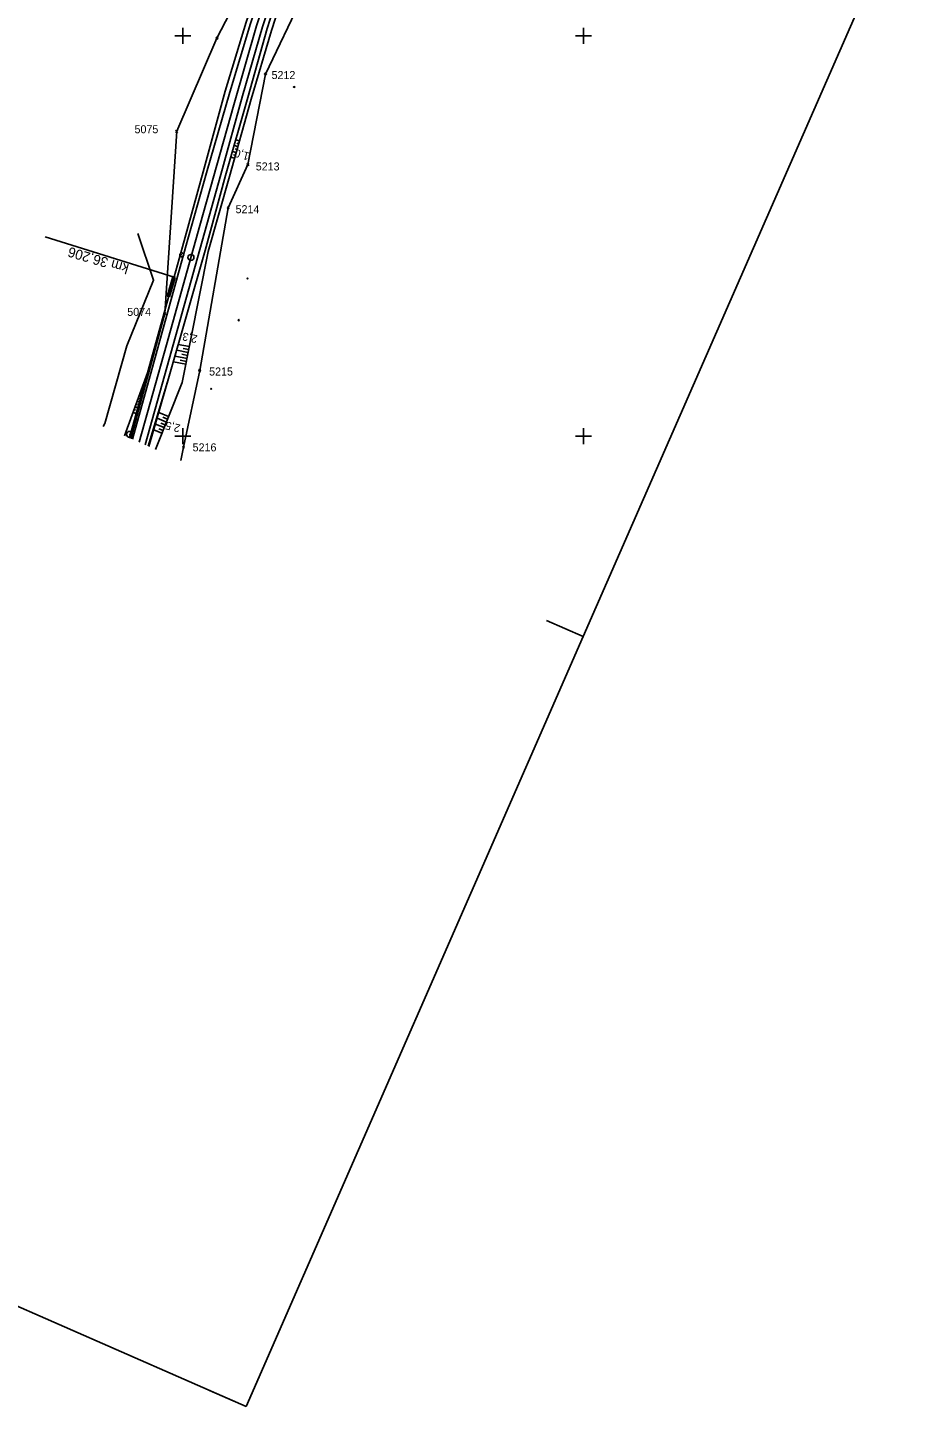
# Model space of a CAD drawing. Extents: x -806856 to -806332, y -1151642 to -1150946.
# Drawn here: x -806638.8 to -806415.8, y -1151642.4 to -1151297.9 of the extents above; entities that cross this region are included whole.
import ezdxf

# ---------------------------------------------------------------- set-up
doc = ezdxf.new("R2010")
doc.units = 0
for name, color, linetype in [('0381KM032-037P - Vrstva 1', 7, 'Continuous'), ('0381KM032-037P - Vrstva 17', 7, 'Continuous'), ('0381KM032-037P - Vrstva 4', 7, 'Continuous'), ('0381KM032-037P - Vrstva 48', 7, 'Continuous'), ('0381KM032-037P - Vrstva 49', 7, 'Continuous'), ('0381KM032-037P - Vrstva 7', 7, 'Continuous'), ('0381KM032-037P - Vrstva 9', 7, 'Continuous'), ('formát', 7, 'Continuous'), ('krizky_1000 - Vrstva 1', 7, 'Continuous'), ('szdc - hran DP', 7, 'Continuous'), ('szdc - szdc_cislo', 7, 'Continuous'), ('szdc - szdc_krizek', 7, 'Continuous'), ('vyt_sit - stávající', 7, 'Continuous')]:
    doc.layers.add(name, color=color, linetype=linetype)

msp = doc.modelspace()

# ---------------------------------------------------------------- linework, layer by layer
at = {"layer": '0381KM032-037P - Vrstva 1'}
for points in [[(-806575.26, -1151278.66), (-806581.61, -1151297.45), (-806587.32, -1151317.2)], [(-806587.32, -1151317.2), (-806595.77, -1151347.36), (-806604.1, -1151377.15), (-806610.94, -1151401.52)]]:
    msp.add_lwpolyline(points, dxfattribs=at)
at = {"layer": '0381KM032-037P - Vrstva 17'}
msp.add_lwpolyline([(-806611.24, -1151349.41), (-806607.31, -1151360.99), (-806614.01, -1151377.45), (-806619.53, -1151396.86), (-806619.89, -1151397.6)], dxfattribs=at)
at = {"layer": '0381KM032-037P - Vrstva 4'}
for points in [[(-806534.73, -1151198.81), (-806545.37, -1151216.39), (-806553.18, -1151229.13), (-806561.58, -1151243.53), (-806567.96, -1151255.6), (-806574.3, -1151269.24), (-806578.76, -1151280.27), (-806579.4, -1151282.54), (-806584.22, -1151296.56), (-806589.48, -1151313.82), (-806594.95, -1151333.92), (-806600.1, -1151352.67), (-806608.81, -1151384.22), (-806613.08, -1151400.58)], [(-806534.14, -1151199.19), (-806544.55, -1151216.75), (-806552.31, -1151229.7), (-806560.71, -1151244.03), (-806567.24, -1151256.24), (-806573.52, -1151269.73), (-806577.97, -1151280.92), (-806578.5, -1151282.67), (-806583.15, -1151296.86), (-806588.26, -1151314.07), (-806594.08, -1151334.22), (-806599.38, -1151352.89), (-806608.02, -1151384.26), (-806612.6, -1151400.79)], [(-806531.11, -1151200.55), (-806541.48, -1151217.8), (-806549.08, -1151230.92), (-806557.69, -1151245.47), (-806564.05, -1151257.36), (-806570.21, -1151270.63), (-806574.62, -1151281.75), (-806575.45, -1151283.67), (-806580.1, -1151297.77), (-806585.12, -1151314.97), (-806590.56, -1151334.63), (-806595.8, -1151353.37), (-806604.61, -1151384.9), (-806609.41, -1151402.19)], [(-806530.22, -1151201.05), (-806540.66, -1151218.65), (-806548.31, -1151231.35), (-806556.78, -1151246.08), (-806563.07, -1151257.89), (-806569.22, -1151271.02), (-806574.1, -1151282.08), (-806574.48, -1151284.1), (-806578.97, -1151298.16), (-806583.83, -1151315.38), (-806589.34, -1151334.88), (-806594.45, -1151353.63), (-806603.42, -1151385.04), (-806608.69, -1151402.5)]]:
    msp.add_lwpolyline(points, dxfattribs=at)
at = {"layer": '0381KM032-037P - Vrstva 48'}
for p, q in [((-806585.91, -1151326.21), (-806586.82, -1151325.96)), ((-806586.71, -1151329.1), (-806587.63, -1151328.85)), ((-806586.91, -1151329.82), (-806587.38, -1151329.7)), ((-806586.31, -1151327.66), (-806587.23, -1151327.4)), ((-806586.51, -1151328.38), (-806586.97, -1151328.25)), ((-806586.11, -1151326.94), (-806586.57, -1151326.81)), ((-806587.11, -1151330.55), (-806588.04, -1151330.29)), ((-806598.39, -1151377.63), (-806601.15, -1151377.08)), ((-806598.54, -1151378.36), (-806599.95, -1151378.08)), ((-806599.27, -1151382.04), (-806602.39, -1151381.42)), ((-806598.98, -1151380.57), (-806601.97, -1151379.98)), ((-806598.69, -1151379.1), (-806601.56, -1151378.53)), ((-806599.12, -1151381.31), (-806600.65, -1151381)), ((-806598.83, -1151379.83), (-806600.3, -1151379.54)), ((-806611.67, -1151391.97), (-806611.36, -1151392.08)), ((-806611.41, -1151391.27), (-806610.85, -1151391.47)), ((-806611.15, -1151390.56), (-806610.9, -1151390.65)), ((-806610.89, -1151389.86), (-806610.44, -1151390.02)), ((-806612.45, -1151394.08), (-806611.67, -1151394.37)), ((-806612.19, -1151393.38), (-806611.83, -1151393.51)), ((-806611.93, -1151392.67), (-806611.26, -1151392.92)), ((-806604.12, -1151396.48), (-806606.45, -1151395.55)), ((-806603.57, -1151395.08), (-806606.03, -1151394.1)), ((-806603.85, -1151395.78), (-806605.04, -1151395.3)), ((-806605.24, -1151399.26), (-806607.28, -1151398.45)), ((-806604.68, -1151397.87), (-806606.87, -1151397)), ((-806604.96, -1151398.57), (-806606.02, -1151398.14)), ((-806604.4, -1151397.17), (-806605.53, -1151396.72))]:
    msp.add_line(p, q, dxfattribs=at)
at = {"layer": '0381KM032-037P - Vrstva 49'}
for p, q in [((-806572.06, -1151312.59), (-806572.42, -1151312.95)), ((-806572.42, -1151312.59), (-806572.06, -1151312.95)), ((-806583.68, -1151360.44), (-806584.03, -1151360.8)), ((-806584.03, -1151360.44), (-806583.68, -1151360.8)), ((-806585.91, -1151370.83), (-806586.27, -1151371.18)), ((-806586.27, -1151370.83), (-806585.91, -1151371.18)), ((-806608.81, -1151384.22), (-806613.38, -1151400.45)), ((-806608.81, -1151384.22), (-806613.08, -1151400.58)), ((-806592.76, -1151387.98), (-806593.11, -1151388.33)), ((-806593.11, -1151387.98), (-806592.75, -1151388.33))]:
    msp.add_line(p, q, dxfattribs=at)
for points in [[(-806520.01, -1151188.39), (-806536.66, -1151214.61), (-806549.93, -1151238.4), (-806571.09, -1151278.57), (-806574.7, -1151288.79), (-806577.92, -1151298.67), (-806582.99, -1151315.77), (-806588.39, -1151335.12), (-806593.7, -1151353.88), (-806600.16, -1151386.57)], [(-806535.85, -1151198.12), (-806546.61, -1151215.57), (-806553.18, -1151229.13), (-806561.58, -1151243.53), (-806567.96, -1151255.6), (-806574.3, -1151269.24), (-806578.76, -1151280.27), (-806579.4, -1151282.54), (-806584.22, -1151296.56), (-806589.48, -1151313.82), (-806594.95, -1151333.92), (-806600.1, -1151352.67), (-806608.81, -1151384.22), (-806614.6, -1151399.91)], [(-806574.1, -1151282.08), (-806574.48, -1151284.1), (-806578.97, -1151298.16), (-806583.83, -1151315.38), (-806589.34, -1151334.88), (-806594.45, -1151353.63), (-806603.42, -1151385.04), (-806608.48, -1151402.59)], [(-806608.69, -1151402.5), (-806603.42, -1151385.04)], [(-806600.16, -1151386.57), (-806606.86, -1151403.3)]]:
    msp.add_lwpolyline(points, dxfattribs=at)
at = {"layer": '0381KM032-037P - Vrstva 7'}
msp.add_line((-806600.34, -1151354.71), (-806600.24, -1151354.71), dxfattribs=at)
for centre, radius in [((-806600.29, -1151354.71), 0.5), ((-806598, -1151355.35), 0.75)]:
    msp.add_circle(centre, radius, dxfattribs=at)
at = {"layer": '0381KM032-037P - Vrstva 9'}
for p, q in [((-806602.2, -1151360.29), (-806634.39, -1151350.17)), ((-806602.49, -1151360.21), (-806603.91, -1151365)), ((-806603.33, -1151365.17), (-806601.91, -1151360.38)), ((-806602.49, -1151360.21), (-806603.06, -1151360.04)), ((-806601.91, -1151360.38), (-806602.49, -1151360.21)), ((-806603.91, -1151365), (-806603.33, -1151365.17))]:
    msp.add_line(p, q, dxfattribs=at)
at = {"layer": 'formát'}
for p, q in [((-806415.83, -1151257.68), (-806500.03, -1151450.06)), ((-806509.19, -1151446.05), (-806500.03, -1151450.06)), ((-806509.19, -1151446.05), (-806500.03, -1151450.06)), ((-806500.03, -1151450.06), (-806584.22, -1151642.44)), ((-806856.31, -1151523.36), (-806584.22, -1151642.44)), ((-806593.38, -1151638.43), (-806584.22, -1151642.44))]:
    msp.add_line(p, q, dxfattribs=at)
at = {"layer": 'krizky_1000 - Vrstva 1'}
for points in [[(-806600, -1151298), (-806600, -1151302)], [(-806500, -1151298), (-806500, -1151302)], [(-806602, -1151300), (-806598, -1151300)], [(-806502, -1151300), (-806498, -1151300)], [(-806600, -1151398), (-806600, -1151402)], [(-806500, -1151398), (-806500, -1151402)], [(-806602, -1151400), (-806598, -1151400)], [(-806502, -1151400), (-806498, -1151400)]]:
    msp.add_lwpolyline(points, dxfattribs=at)
at = {"layer": 'szdc - hran DP'}
for p, q in [((-806591.51, -1151300.57), (-806576.79, -1151271.69)), ((-806561.98, -1151273.31), (-806579.39, -1151309.52)), ((-806601.55, -1151323.84), (-806591.51, -1151300.57)), ((-806579.39, -1151309.52), (-806583.8, -1151332.16)), ((-806604.52, -1151369.36), (-806601.55, -1151323.84)), ((-806583.8, -1151332.16), (-806588.67, -1151342.95)), ((-806588.67, -1151342.95), (-806595.8, -1151383.59)), ((-806612.97, -1151400.63), (-806604.52, -1151369.36)), ((-806595.8, -1151383.59), (-806599.86, -1151402.77)), ((-806599.86, -1151402.77), (-806600.56, -1151406.06))]:
    msp.add_line(p, q, dxfattribs=at)
at = {"layer": 'szdc - szdc_krizek'}
for p, q in [((-806591.24, -1151300.83), (-806591.78, -1151300.3)), ((-806591.78, -1151300.83), (-806591.24, -1151300.3)), ((-806579.12, -1151309.78), (-806579.66, -1151309.26)), ((-806579.66, -1151309.78), (-806579.12, -1151309.26)), ((-806601.29, -1151324.1), (-806601.82, -1151323.57)), ((-806601.82, -1151324.1), (-806601.29, -1151323.57)), ((-806583.54, -1151332.43), (-806584.07, -1151331.9)), ((-806584.07, -1151332.43), (-806583.54, -1151331.9)), ((-806588.41, -1151343.22), (-806588.94, -1151342.69)), ((-806588.94, -1151343.22), (-806588.41, -1151342.69)), ((-806604.26, -1151369.62), (-806604.79, -1151369.09)), ((-806604.79, -1151369.62), (-806604.26, -1151369.09)), ((-806595.54, -1151383.85), (-806596.07, -1151383.32)), ((-806596.07, -1151383.85), (-806595.54, -1151383.32)), ((-806599.59, -1151403.03), (-806600.13, -1151402.51)), ((-806600.13, -1151403.03), (-806599.59, -1151402.51))]:
    msp.add_line(p, q, dxfattribs=at)
at = {"layer": 'vyt_sit - stávající'}
msp.add_line((-806613.39, -1151399.56), (-806613.29, -1151399.56), dxfattribs=at)
msp.add_circle((-806613.33, -1151399.56), 0.756, dxfattribs=at)

# ---------------------------------------------------------------- texts
at = {"layer": '0381KM032-037P - Vrstva 48'}
for s, rotation, p in [('1,0', 164.2247, (-806583.24, -1151329.23)), ('2,3', 167.817, (-806596.23, -1151374.85)), ('2,5', 166.3296, (-806600.51, -1151397.17))]:
    msp.add_text(s, height=2, rotation=rotation, dxfattribs=at).set_placement(p)
at = {"layer": '0381KM032-037P - Vrstva 9'}
msp.add_text('km 36,206', height=2.5, rotation=163.5076, dxfattribs=at).set_placement((-806613.29, -1151357.1))
at = {"layer": 'szdc - szdc_cislo'}
for s, p in [('5212', (-806577.87, -1151310.78)), ('5075', (-806612.09, -1151324.32)), ('5213', (-806581.81, -1151333.61)), ('5214', (-806586.85, -1151344.3)), ('5074', (-806613.9, -1151369.95)), ('5215', (-806593.46, -1151384.85)), ('5216', (-806597.58, -1151403.8))]:
    msp.add_text(s, height=2, dxfattribs=at).set_placement(p)

doc.saveas('drawing.dxf')
